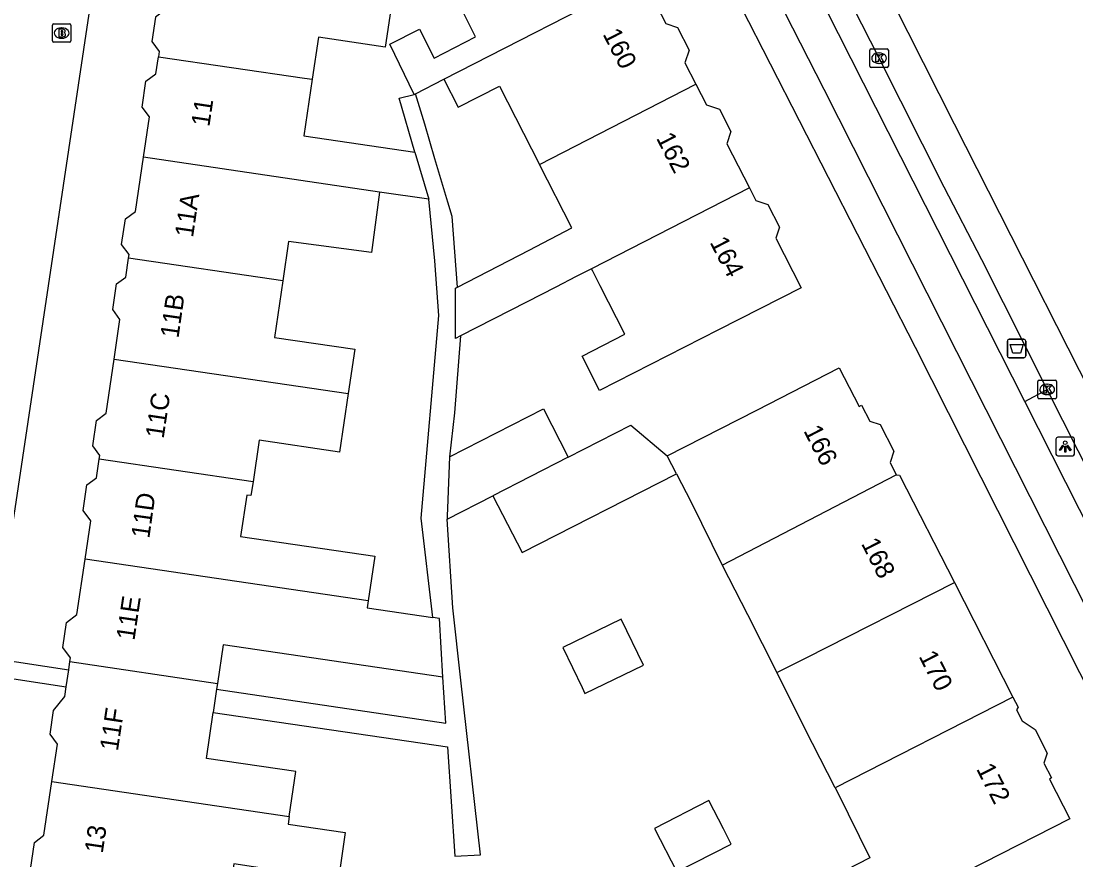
# Model space of a CAD drawing. Extents: x 162250 to 162654, y 380744 to 381605.
# Drawn here: x 162352.5 to 162409.4, y 381504 to 381549.2 of the extents above; entities that cross this region are included whole.
import ezdxf

# ---------------------------------------------------------------- set-up
doc = ezdxf.new("R2010")
doc.units = 0
for name, color, linetype in [('IMGEO_Afvalbak', 7, 'Continuous'), ('IMGEO_Berm_open', 7, 'Continuous'), ('IMGEO_Brandkraan', 7, 'Continuous'), ('IMGEO_Fietspad_gesloten', 7, 'Continuous'), ('IMGEO_Kolk', 7, 'Continuous'), ('IMGEO_Lichtpunt', 7, 'Continuous'), ('IMGEO_Pand', 7, 'Continuous'), ('IMGEO_Pand_nummerreeks', 7, 'Continuous'), ('IMGEO_Parkeervlak_open', 7, 'Continuous'), ('IMGEO_Rijbaan_regionaal_gesloten', 7, 'Continuous'), ('IMGEO_Voetpad_open', 7, 'Continuous')]:
    doc.layers.add(name, color=color, linetype=linetype)

msp = doc.modelspace()

# ---------------------------------------------------------------- linework, layer by layer
at = {"layer": 'IMGEO_Afvalbak'}
for p, q in [((162405.739, 381531.177), (162405.739, 381531.977)), ((162405.739, 381531.977), (162405.739, 381531.177)), ((162405.839, 381532.077), (162406.629, 381532.077)), ((162406.629, 381532.077), (162405.839, 381532.077)), ((162406.729, 381531.977), (162406.729, 381531.177)), ((162406.729, 381531.177), (162406.729, 381531.977)), ((162406.629, 381531.077), (162405.839, 381531.077)), ((162405.839, 381531.077), (162406.629, 381531.077))]:
    msp.add_line(p, q, dxfattribs=at)
msp.add_lwpolyline([(162405.882, 381531.791), (162406.586, 381531.791), (162406.437, 381531.321), (162406.031, 381531.321), (162405.882, 381531.791)], dxfattribs=at)
for centre, start, end in [((162405.839, 381531.977), 90, 180), ((162405.839, 381531.977), 90, 180), ((162406.629, 381531.977), 0, 90), ((162406.629, 381531.977), 360, 90), ((162405.839, 381531.177), 180, 270), ((162405.839, 381531.177), 180, 270), ((162406.629, 381531.177), 270, 0), ((162406.629, 381531.177), 270, 0)]:
    msp.add_arc(centre, 0.1, start, end, dxfattribs=at)
at = {"layer": 'IMGEO_Berm_open'}
msp.add_lwpolyline([(162406.674, 381528.711), (162407.881, 381529.368)], dxfattribs=at)
at = {"layer": 'IMGEO_Brandkraan'}
for p, q in [((162354.186, 381548.178), (162354.186, 381549.03)), ((162354.261, 381549.104), (162355.113, 381549.104)), ((162354.674, 381548.884), (162354.699, 381548.884)), ((162355.187, 381549.03), (162355.187, 381548.178)), ((162355.113, 381548.104), (162354.261, 381548.104)), ((162354.697, 381548.324), (162354.672, 381548.324))]:
    msp.add_line(p, q, dxfattribs=at)
for points in [[(162354.186, 381548.178), (162354.186, 381549.03)], [(162354.261, 381549.104), (162355.113, 381549.104)], [(162354.534, 381548.804), (162354.534, 381548.404), (162354.747, 381548.404)], [(162354.765, 381548.804), (162354.534, 381548.804)], [(162354.713, 381548.723), (162354.659, 381548.723), (162354.659, 381548.647)], [(162354.659, 381548.647), (162354.712, 381548.647)], [(162355.187, 381549.03), (162355.187, 381548.178)], [(162355.113, 381548.104), (162354.261, 381548.104)], [(162354.721, 381548.571), (162354.659, 381548.571), (162354.659, 381548.49)], [(162354.659, 381548.49), (162354.721, 381548.49)]]:
    msp.add_lwpolyline(points, dxfattribs=at)
for centre, radius, start, end in [((162354.263, 381549.028), 0.0765, 91.552, 178.448), ((162354.263, 381549.028), 0.0765, 91.552, 178.448), ((162354.714, 381548.685), 0.0379, 267.8285, 90.9355), ((162354.769, 381548.659), 0.145, 59.4692, 91.5367), ((162354.794, 381548.706), 0.0922, 285.5137, 58.1501), ((162355.111, 381549.028), 0.0765, 1.552, 88.448), ((162355.111, 381549.028), 0.0765, 1.552, 88.448), ((162354.263, 381548.18), 0.0765, 181.552, 268.448), ((162354.263, 381548.18), 0.0765, 181.552, 268.448), ((162354.722, 381548.53), 0.0404, 269.8759, 90.5077), ((162354.753, 381548.655), 0.251, 268.6676, 293.5347), ((162354.799, 381548.514), 0.105, 301.3115, 78.989), ((162355.111, 381548.18), 0.0765, 271.552, 358.448), ((162355.111, 381548.18), 0.0765, 271.552, 358.448)]:
    msp.add_arc(centre, radius, start, end, dxfattribs=at)
for centre, major_axis, ratio, start_param, end_param in [((162354.673, 381548.604), (-0.387, 0.002), 0.722429, 4.712389, 7.853982), ((162354.698, 381548.604), (-0.39, 0.002), 0.717154, 1.570796, 4.712389)]:
    msp.add_ellipse(centre, major_axis=major_axis, ratio=ratio, start_param=start_param, end_param=end_param, dxfattribs=at)
at = {"layer": 'IMGEO_Fietspad_gesloten'}
for points in [[(162373.585, 381588.91), (162375.873, 381584.438), (162383.286, 381570.262), (162389.481, 381558.016), (162395.82, 381545.575), (162418.876, 381500), (162423.197, 381491.458), (162446.904, 381444.637), (162457.136, 381424.429), (162474.154, 381390.568), (162476.043, 381386.824)], [(162406.674, 381528.711), (162395.284, 381551.21)], [(162471.376, 381400.747), (162459.052, 381425.24), (162448.774, 381445.553), (162406.674, 381528.711)]]:
    msp.add_lwpolyline(points, dxfattribs=at)
at = {"layer": 'IMGEO_Kolk'}
for p, q in [((162398.312, 381546.821), (162398.312, 381547.673)), ((162398.387, 381547.747), (162399.239, 381547.747)), ((162398.8, 381547.527), (162398.825, 381547.527)), ((162399.313, 381547.673), (162399.313, 381546.821)), ((162398.823, 381546.967), (162398.798, 381546.967)), ((162399.239, 381546.747), (162398.387, 381546.747)), ((162407.458, 381529.868), (162408.31, 381529.868)), ((162407.383, 381528.942), (162407.383, 381529.794)), ((162407.871, 381529.648), (162407.896, 381529.648)), ((162408.384, 381529.794), (162408.384, 381528.942)), ((162408.31, 381528.868), (162407.458, 381528.868)), ((162407.894, 381529.088), (162407.869, 381529.088))]:
    msp.add_line(p, q, dxfattribs=at)
for points in [[(162398.312, 381546.821), (162398.312, 381547.673)], [(162398.387, 381547.747), (162399.239, 381547.747)], [(162399.313, 381547.673), (162399.313, 381546.821)], [(162398.633, 381547.447), (162398.756, 381547.447), (162398.756, 381547.296), (162398.886, 381547.447), (162399.05, 381547.447), (162398.904, 381547.296), (162399.057, 381547.047), (162398.905, 381547.047), (162398.82, 381547.211), (162398.756, 381547.144), (162398.756, 381547.047), (162398.633, 381547.047), (162398.633, 381547.447)], [(162399.239, 381546.747), (162398.387, 381546.747)], [(162407.458, 381529.868), (162408.31, 381529.868)], [(162407.383, 381528.942), (162407.383, 381529.794)], [(162407.704, 381529.568), (162407.827, 381529.568), (162407.827, 381529.417), (162407.957, 381529.568), (162408.121, 381529.568), (162407.975, 381529.417), (162408.128, 381529.168), (162407.976, 381529.168), (162407.891, 381529.332), (162407.827, 381529.265), (162407.827, 381529.168), (162407.704, 381529.168), (162407.704, 381529.568)], [(162408.384, 381529.794), (162408.384, 381528.942)], [(162408.31, 381528.868), (162407.458, 381528.868)]]:
    msp.add_lwpolyline(points, dxfattribs=at)
for centre, start, end in [((162398.389, 381547.671), 91.552, 178.448), ((162398.389, 381547.671), 91.552, 178.448), ((162399.237, 381547.671), 1.552, 88.448), ((162399.237, 381547.671), 1.552, 88.448), ((162398.389, 381546.823), 181.552, 268.448), ((162398.389, 381546.823), 181.552, 268.448), ((162399.237, 381546.823), 271.552, 358.448), ((162399.237, 381546.823), 271.552, 358.448), ((162407.46, 381529.792), 91.552, 178.448), ((162407.46, 381529.792), 91.552, 178.448), ((162408.308, 381529.792), 1.552, 88.448), ((162408.308, 381529.792), 1.552, 88.448), ((162407.46, 381528.944), 181.552, 268.448), ((162407.46, 381528.944), 181.552, 268.448), ((162408.308, 381528.944), 271.552, 358.448), ((162408.308, 381528.944), 271.552, 358.448)]:
    msp.add_arc(centre, 0.0765, start, end, dxfattribs=at)
for centre, major_axis, ratio, start_param, end_param in [((162398.799, 381547.247), (-0.387, 0.002), 0.722429, 4.712389, 7.853982), ((162398.824, 381547.247), (-0.39, 0.002), 0.717154, 1.570796, 4.712389), ((162407.87, 381529.368), (-0.387, 0.002), 0.722429, 4.712389, 7.853982), ((162407.895, 381529.368), (-0.39, 0.002), 0.717154, 1.570796, 4.712389)]:
    msp.add_ellipse(centre, major_axis=major_axis, ratio=ratio, start_param=start_param, end_param=end_param, dxfattribs=at)
at = {"layer": 'IMGEO_Lichtpunt'}
for p, q in [((162408.359, 381526.691), (162408.359, 381525.884)), ((162408.359, 381526.691), (162408.359, 381525.884)), ((162409.261, 381526.786), (162408.453, 381526.786)), ((162409.261, 381526.786), (162408.453, 381526.786)), ((162409.355, 381525.884), (162409.355, 381526.691)), ((162409.355, 381525.884), (162409.355, 381526.691)), ((162408.453, 381525.79), (162409.261, 381525.79)), ((162408.453, 381525.79), (162409.261, 381525.79))]:
    msp.add_line(p, q, dxfattribs=at)
for points in [[(162408.733, 381526.355), (162408.772, 381526.327), (162408.584, 381526.065), (162408.546, 381526.092), (162408.733, 381526.355)], [(162408.835, 381526.307), (162408.882, 381526.307), (162408.882, 381525.985), (162408.835, 381525.985), (162408.835, 381526.307)], [(162408.945, 381526.327), (162408.983, 381526.354), (162409.17, 381526.092), (162409.131, 381526.064), (162408.945, 381526.327)]]:
    msp.add_lwpolyline(points, dxfattribs=at)
msp.add_circle((162408.858, 381526.489), 0.0994, dxfattribs=at)
for centre, start, end in [((162408.453, 381526.691), 90, 180), ((162408.453, 381526.691), 90, 180), ((162409.261, 381526.691), 0, 90), ((162409.261, 381526.691), 0, 90), ((162408.453, 381525.884), 180, 270), ((162408.453, 381525.884), 180, 270), ((162409.261, 381525.884), 270, 0), ((162409.261, 381525.884), 270, 360)]:
    msp.add_arc(centre, 0.0946, start, end, dxfattribs=at)
at = {"layer": 'IMGEO_Pand'}
for points in [[(162360.753, 381552.779), (162360.327, 381549.89), (162359.75, 381549.461), (162359.555, 381548.141), (162359.952, 381547.607), (162359.911, 381547.328)], [(162373.709, 381545.286), (162372.399, 381547.994), (162373.994, 381548.809), (162374.787, 381547.256), (162377.034, 381548.403), (162376.376, 381549.692), (162374.779, 381552.819), (162375.316, 381553.093)], [(162375.313, 381546.109), (162386.023, 381551.605)], [(162386.023, 381551.605), (162387.294, 381549.116), (162387.927, 381548.911), (162388.553, 381547.687), (162388.331, 381547.003), (162388.92, 381545.85)], [(162372.603, 381550.922), (162372.56, 381550.628), (162372.342, 381549.148), (162372.151, 381547.849), (162368.544, 381548.38), (162368.21, 381546.113)], [(162359.1, 381541.898), (162359.421, 381544.074), (162359.031, 381544.598), (162359.238, 381546), (162359.774, 381546.398), (162359.911, 381547.328)], [(162359.911, 381547.328), (162367.801, 381546.167), (162368.21, 381546.113)], [(162368.21, 381546.113), (162367.761, 381543.063), (162373.757, 381542.179)], [(162373.782, 381545.323), (162375.313, 381546.109)], [(162375.313, 381546.109), (162376.084, 381544.599), (162378.321, 381545.741), (162380.478, 381541.517)], [(162380.478, 381541.517), (162388.92, 381545.85)], [(162388.92, 381545.85), (162389.492, 381544.731), (162390.197, 381544.503), (162390.813, 381543.296), (162390.598, 381542.629), (162391.811, 381540.255)], [(162373.709, 381545.286), (162373.782, 381545.323)], [(162358.299, 381536.452), (162358.327, 381536.644), (162357.923, 381537.189), (162358.127, 381538.577), (162358.67, 381538.98), (162359.1, 381541.898)], [(162371.837, 381540.023), (162359.1, 381541.898)], [(162373.757, 381542.179), (162374.51, 381539.63)], [(162376.062, 381534.886), (162379.915, 381536.886), (162382.23, 381538.088), (162380.478, 381541.517)], [(162391.811, 381540.255), (162392.165, 381539.562), (162392.799, 381539.356), (162393.427, 381538.126), (162393.235, 381537.532), (162394.601, 381534.858), (162390.149, 381532.584), (162383.725, 381529.303), (162382.775, 381531.163), (162385.092, 381532.346), (162383.752, 381534.969), (162383.352, 381535.753), (162383.287, 381535.88)], [(162391.811, 381540.255), (162383.287, 381535.88)], [(162371.837, 381540.023), (162371.406, 381536.766), (162366.938, 381537.357), (162366.624, 381535.227)], [(162374.51, 381539.63), (162371.837, 381540.023)], [(162357.519, 381531.002), (162357.836, 381533.151), (162357.445, 381533.677), (162357.649, 381535.06), (162358.148, 381535.431), (162358.299, 381536.452)], [(162366.624, 381535.227), (162358.299, 381536.452)], [(162383.287, 381535.88), (162382.467, 381535.459), (162381.355, 381534.889), (162379.781, 381534.081), (162376.211, 381532.256)], [(162366.624, 381535.227), (162366.174, 381532.177), (162370.509, 381531.538), (162370.156, 381529.142)], [(162376.211, 381532.256), (162375.94, 381532.118), (162375.949, 381534.828), (162376.062, 381534.886)], [(162356.712, 381525.611), (162356.742, 381525.812), (162356.363, 381526.323), (162356.565, 381527.698), (162357.09, 381528.088), (162357.519, 381531.002)], [(162357.519, 381531.002), (162370.156, 381529.142)], [(162387.38, 381525.79), (162392.211, 381528.258), (162396.663, 381530.532), (162397.728, 381528.447), (162397.865, 381528.517), (162398.302, 381527.662), (162398.872, 381527.477), (162399.606, 381526.041), (162399.406, 381525.425), (162399.741, 381524.769)], [(162370.156, 381529.142), (162369.689, 381525.986), (162365.346, 381526.626), (162365.016, 381524.389)], [(162375.622, 381525.729), (162380.701, 381528.324), (162382.035, 381525.712)], [(162382.035, 381525.712), (162385.407, 381527.435), (162387.38, 381525.79)], [(162355.953, 381520.216), (162356.258, 381522.282), (162355.845, 381522.838), (162356.049, 381524.222), (162356.564, 381524.605), (162356.712, 381525.611)], [(162365.016, 381524.389), (162356.712, 381525.611)], [(162375.622, 381525.729), (162375.516, 381522.967), (162375.5, 381522.541), (162375.493, 381522.37)], [(162382.035, 381525.712), (162377.97, 381523.636)], [(162387.874, 381524.823), (162387.38, 381525.79)], [(162377.97, 381523.636), (162379.539, 381520.565), (162387.874, 381524.823)], [(162387.874, 381524.823), (162388.664, 381523.278), (162390.344, 381519.891)], [(162390.344, 381519.891), (162399.741, 381524.769)], [(162399.741, 381524.769), (162399.912, 381524.749), (162402.874, 381518.951)], [(162365.016, 381524.389), (162364.905, 381523.637), (162364.675, 381523.671), (162364.346, 381521.437), (162371.584, 381520.371), (162371.229, 381517.967)], [(162375.493, 381522.37), (162377.97, 381523.636)], [(162355.137, 381514.681), (162355.166, 381514.879), (162354.745, 381515.446), (162354.945, 381516.8), (162355.512, 381517.222), (162355.953, 381520.216)], [(162371.229, 381517.967), (162355.953, 381520.216)], [(162390.344, 381519.891), (162391.707, 381517.221), (162393.289, 381514.087)], [(162393.289, 381514.087), (162394.867, 381514.888), (162402.874, 381518.951)], [(162402.874, 381518.951), (162406.037, 381512.759)], [(162371.229, 381517.967), (162371.174, 381517.591), (162374.724, 381517.067)], [(162375.255, 381513.842), (162375.078, 381517.015), (162374.724, 381517.067)], [(162381.733, 381515.445), (162382.782, 381513.276), (162382.936, 381512.957), (162386.093, 381514.483), (162384.89, 381516.971), (162381.733, 381515.445)], [(162375.255, 381513.842), (162363.409, 381515.589), (162363.102, 381513.508)], [(162355.072, 381514.24), (162355.137, 381514.681)], [(162355.137, 381514.681), (162363.102, 381513.508)], [(162354.936, 381513.318), (162355.072, 381514.24)], [(162396.447, 381507.86), (162395.221, 381510.26), (162393.289, 381514.087)], [(162363.102, 381513.508), (162363.054, 381513.185)], [(162354.162, 381508.214), (162354.459, 381510.228), (162354.065, 381510.758), (162354.253, 381512.035), (162354.86, 381512.801), (162354.936, 381513.318)], [(162363.054, 381513.185), (162362.87, 381511.937)], [(162406.037, 381512.759), (162396.447, 381507.86)], [(162406.037, 381512.759), (162406.311, 381512.222), (162406.219, 381512.079), (162406.525, 381511.479), (162407.239, 381511.017), (162407.889, 381509.744), (162407.711, 381509.195), (162408.116, 381508.401), (162408.002, 381508.342), (162409.098, 381506.196), (162399.784, 381501.438), (162400.517, 381500), (162400.881, 381499.285)], [(162366.97, 381506.329), (162367.326, 381508.746), (162362.505, 381509.456), (162362.87, 381511.937)], [(162353.367, 381502.796), (162353.388, 381502.939), (162353.003, 381503.457), (162353.219, 381504.924), (162353.733, 381505.306), (162354.162, 381508.214)], [(162354.162, 381508.214), (162366.97, 381506.329)], [(162396.447, 381507.86), (162396.563, 381507.633), (162398.319, 381504.092), (162396.38, 381503.102), (162395.71, 381502.759), (162395.16, 381502.478), (162395.911, 381501.008), (162395.773, 381500.948), (162392.515, 381499.525)], [(162387.889, 381503.332), (162390.828, 381504.834), (162390.777, 381504.934), (162390.406, 381505.661), (162389.629, 381507.181), (162386.69, 381505.679), (162387.889, 381503.332)], [(162366.97, 381506.329), (162366.909, 381505.912), (162369.996, 381505.458), (162369.623, 381502.935), (162366.536, 381503.389), (162366.113, 381503.451), (162363.982, 381503.765), (162363.617, 381501.287)]]:
    msp.add_lwpolyline(points, dxfattribs=at)
at = {"layer": 'IMGEO_Parkeervlak_open'}
for points in [[(162407.881, 381529.368), (162404.362, 381536.357), (162402.33, 381540.282), (162398.81, 381547.248), (162396.502, 381551.808)], [(162451.347, 381443.613), (162450.046, 381446.175), (162448.732, 381448.765), (162441.543, 381462.942), (162439.388, 381467.195), (162438.961, 381468.029), (162428.315, 381489.033), (162427.992, 381489.702), (162424.381, 381496.806), (162422.775, 381500), (162420.516, 381504.491), (162416.582, 381512.206), (162416.272, 381512.782), (162407.881, 381529.368)]]:
    msp.add_lwpolyline(points, dxfattribs=at)
at = {"layer": 'IMGEO_Rijbaan_regionaal_gesloten'}
msp.add_lwpolyline([(162379.636, 381588.378), (162392.859, 381563.507), (162402.855, 381543.709), (162412.668, 381524.385), (162425.065, 381500), (162437.86, 381474.688), (162449.303, 381452.467), (162451.987, 381447.126), (162459.635, 381431.909), (162469.338, 381412.429), (162476.05, 381399.207), (162475.732, 381399.044)], dxfattribs=at)
at = {"layer": 'IMGEO_Voetpad_open'}
for points in [[(162371.772, 381588.094), (162370.283, 381588.375), (162363.369, 381585.251), (162361.6, 381584.081), (162363.286, 381580.314), (162362.669, 381579.584), (162359.448, 381578.123), (162359.403, 381573.306), (162358.055, 381562.41), (162350.929, 381514.861)], [(162474.869, 381385.175), (162465.732, 381403.337), (162448.748, 381437.096), (162445.289, 381443.846), (162433.372, 381467.098), (162422.628, 381488.367), (162420.377, 381492.822), (162416.751, 381500), (162400.772, 381531.631), (162381.991, 381568.34), (162371.772, 381588.094)], [(162373.757, 381542.179), (162372.897, 381545.09), (162373.709, 381545.286)], [(162376.062, 381534.886), (162375.77, 381538.697), (162375.537, 381539.48), (162374.837, 381541.812), (162374.291, 381543.683), (162373.782, 381545.323)], [(162374.724, 381517.067), (162374.086, 381522.421), (162375.04, 381533.368), (162374.836, 381536.312), (162374.51, 381539.63)], [(162376.211, 381532.256), (162375.887, 381528.098), (162375.622, 381525.729)], [(162362.87, 381511.937), (162375.507, 381510.076), (162375.903, 381504.176), (162377.291, 381504.261), (162376.237, 381513.67), (162375.804, 381517.584), (162375.493, 381522.37)], [(162350.929, 381514.861), (162355.072, 381514.24)], [(162350.791, 381513.94), (162354.936, 381513.318)], [(162363.054, 381513.185), (162375.421, 381511.363), (162375.255, 381513.842)]]:
    msp.add_lwpolyline(points, dxfattribs=at)

# ---------------------------------------------------------------- texts
at = {"layer": 'IMGEO_Pand_nummerreeks'}
for s, rotation, p in [('160', 297.2153, (162383.87, 381548.551)), ('11', 81.5032, (162362.658, 381543.514)), ('162', 297.2153, (162386.759, 381542.936)), ('11A', 81.635, (162361.775, 381537.536)), ('164', 297.2153, (162389.651, 381537.313)), ('11B', 81.8528, (162360.99, 381532.101)), ('11C', 81.4861, (162360.19, 381526.684)), ('166', 297.0663, (162394.711, 381527.144)), ('11D', 81.9919, (162359.417, 381521.294)), ('168', 297.0657, (162397.822, 381521.056)), ('11E', 81.6121, (162358.615, 381515.788)), ('170', 297.0657, (162400.93, 381514.972)), ('11F', 81.4288, (162357.721, 381509.82)), ('172', 297.0663, (162404.036, 381508.893)), ('13', 81.6522, (162356.903, 381504.301))]:
    msp.add_text(s, height=1, rotation=rotation, dxfattribs=at).set_placement(p)

doc.saveas('drawing.dxf')
